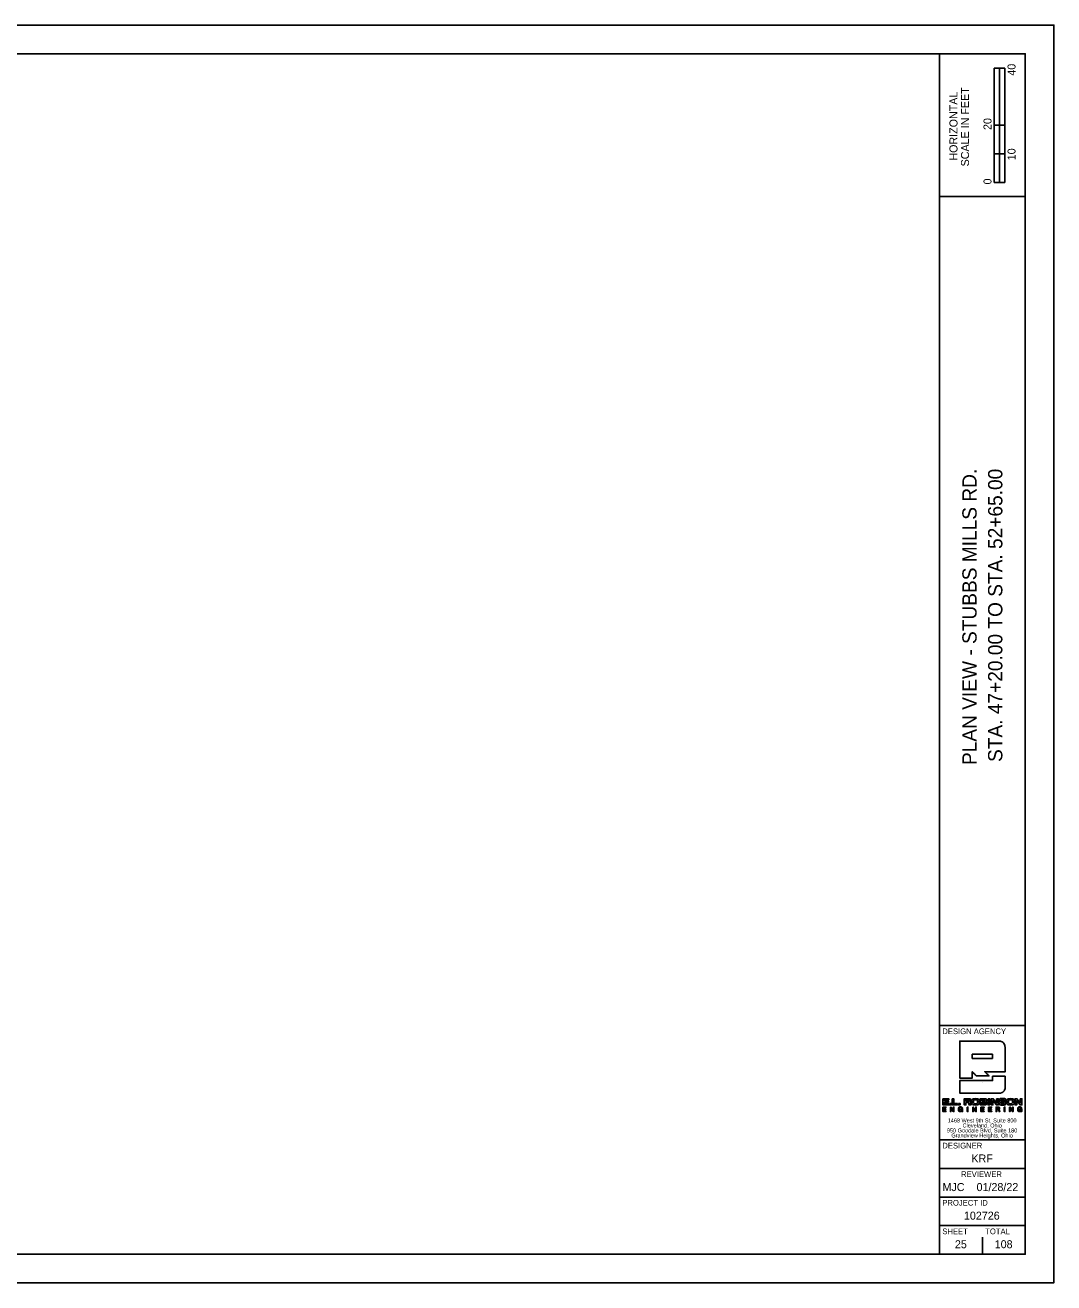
# Model space of a CAD drawing. Extents: x -1.8 to 34.2, y 5.2 to 27.2.
# Drawn here: x 16.19 to 34.18, y 5.18 to 27.18 of the extents above; entities that cross this region are included whole.
import ezdxf

# ---------------------------------------------------------------- set-up
doc = ezdxf.new("R2010")
doc.units = 0
for name, color, linetype in [('SH_Border', 7, 'Continuous'), ('SH_Cut_Line', 7, 'Continuous'), ('SH_Data', 7, 'Continuous')]:
    doc.layers.add(name, color=color, linetype=linetype)

msp = doc.modelspace()

# ---------------------------------------------------------------- linework, layer by layer
at = {"layer": 'SH_Border'}
for p, q in [((32.177, 5.678), (32.177, 26.678)), ((32.177, 24.178), (33.677, 24.178)), ((32.177, 9.678), (33.677, 9.678)), ((32.177, 7.678), (33.677, 7.678)), ((32.177, 7.178), (33.677, 7.178)), ((32.177, 6.678), (33.677, 6.678)), ((32.177, 6.178), (33.677, 6.178))]:
    msp.add_line(p, q, dxfattribs=at)
msp.add_lwpolyline([(1.677, 26.678), (33.677, 26.678), (33.677, 5.678), (1.677, 5.678)], close=True, dxfattribs=at)
at = {"layer": 'SH_Cut_Line'}
msp.add_lwpolyline([(0.177, 5.178), (34.177, 5.178), (34.177, 27.178), (0.177, 27.178)], close=True, dxfattribs=at)
at = {"layer": 'SH_Data'}
for p, q in [((33.133, 24.428), (33.133, 26.428)), ((33.321, 26.428), (33.133, 26.428)), ((33.133, 25.428), (33.133, 26.428)), ((33.133, 26.428), (33.227, 26.428)), ((33.227, 26.428), (33.228, 26.428)), ((33.228, 26.428), (33.228, 25.428)), ((33.321, 26.428), (33.321, 24.428)), ((33.228, 25.428), (33.133, 25.428)), ((33.32, 25.428), (33.227, 25.428)), ((33.227, 25.428), (33.227, 24.928)), ((33.32, 24.928), (33.32, 25.428)), ((33.227, 24.928), (33.133, 24.928)), ((33.133, 24.928), (33.133, 24.428)), ((33.227, 24.428), (33.227, 24.928)), ((33.227, 24.928), (33.32, 24.928)), ((33.321, 24.428), (33.133, 24.428)), ((33.133, 24.428), (33.227, 24.428)), ((33.106, 9.18), (32.751, 9.18)), ((32.751, 9.18), (32.751, 9.103)), ((32.751, 9.103), (33.106, 9.103)), ((33.106, 9.103), (33.106, 9.18)), ((32.927, 8.678), (32.927, 8.678)), ((32.639, 8.378), (32.639, 8.351)), ((32.92, 8.379), (32.92, 8.356)), ((32.92, 8.337), (32.92, 8.311)), ((33.178, 8.243), (33.178, 8.216)), ((33.178, 8.216), (33.2, 8.216)), ((32.927, 5.678), (32.927, 5.978)), ((32.552, 5.853), (32.552, 5.853))]:
    msp.add_line(p, q, dxfattribs=at)
for points in [[(32.236, 8.399), (32.338, 8.399), (32.338, 8.378), (32.266, 8.378), (32.266, 8.356), (32.334, 8.356), (32.334, 8.336), (32.266, 8.336), (32.266, 8.311), (32.339, 8.311), (32.339, 8.29), (32.236, 8.29), (32.236, 8.399)], [(32.397, 8.399), (32.426, 8.399), (32.426, 8.312), (32.492, 8.312), (32.492, 8.29), (32.397, 8.29), (32.397, 8.399)], [(33.028, 8.399), (33.057, 8.399), (33.057, 8.29), (33.028, 8.29), (33.028, 8.399)], [(33.176, 8.399), (33.204, 8.399), (33.204, 8.29), (33.172, 8.29), (33.113, 8.366), (33.113, 8.366), (33.113, 8.29), (33.084, 8.29), (33.084, 8.399), (33.118, 8.399), (33.175, 8.323), (33.176, 8.323), (33.176, 8.399)], [(33.59, 8.399), (33.618, 8.399), (33.618, 8.29), (33.586, 8.29), (33.527, 8.366), (33.527, 8.366), (33.527, 8.29), (33.498, 8.29), (33.498, 8.399), (33.532, 8.399), (33.589, 8.323), (33.59, 8.323), (33.59, 8.399)], [(32.236, 8.252), (32.29, 8.252), (32.29, 8.243), (32.247, 8.243), (32.247, 8.218), (32.287, 8.218), (32.287, 8.21), (32.247, 8.21), (32.247, 8.183), (32.291, 8.183), (32.291, 8.174), (32.236, 8.174), (32.236, 8.252)], [(32.352, 8.316), (32.381, 8.316), (32.381, 8.29), (32.352, 8.29), (32.352, 8.316)], [(32.368, 8.252), (32.379, 8.252), (32.421, 8.189), (32.421, 8.189), (32.421, 8.252), (32.431, 8.252), (32.431, 8.174), (32.419, 8.174), (32.378, 8.237), (32.378, 8.237), (32.378, 8.174), (32.368, 8.174), (32.368, 8.252)], [(32.508, 8.316), (32.537, 8.316), (32.537, 8.29), (32.508, 8.29), (32.508, 8.316)], [(32.664, 8.252), (32.674, 8.252), (32.674, 8.174), (32.664, 8.174), (32.664, 8.252)], [(32.758, 8.252), (32.769, 8.252), (32.81, 8.189), (32.81, 8.189), (32.81, 8.252), (32.82, 8.252), (32.82, 8.174), (32.809, 8.174), (32.768, 8.237), (32.767, 8.237), (32.767, 8.174), (32.758, 8.174), (32.758, 8.252)], [(32.903, 8.252), (32.957, 8.252), (32.957, 8.243), (32.914, 8.243), (32.914, 8.218), (32.954, 8.218), (32.954, 8.21), (32.914, 8.21), (32.914, 8.183), (32.958, 8.183), (32.958, 8.174), (32.903, 8.174), (32.903, 8.252)], [(33.035, 8.252), (33.089, 8.252), (33.089, 8.243), (33.046, 8.243), (33.046, 8.218), (33.086, 8.218), (33.086, 8.21), (33.046, 8.21), (33.046, 8.183), (33.09, 8.183), (33.09, 8.174), (33.035, 8.174), (33.035, 8.252)], [(33.309, 8.252), (33.32, 8.252), (33.32, 8.174), (33.309, 8.174), (33.309, 8.252)], [(33.403, 8.252), (33.414, 8.252), (33.455, 8.189), (33.456, 8.189), (33.456, 8.252), (33.465, 8.252), (33.465, 8.174), (33.454, 8.174), (33.413, 8.237), (33.413, 8.237), (33.413, 8.174), (33.403, 8.174), (33.403, 8.252)]]:
    msp.add_lwpolyline(points, dxfattribs=at)
for points, degree in [([(32.533, 8.76), (32.533, 8.763), (32.533, 9.402), (32.533, 9.405)], 2), ([(32.533, 9.405), (32.536, 9.405), (33.207, 9.405), (33.21, 9.405), (33.273, 9.405), (33.324, 9.354), (33.324, 9.291)], 3), ([(33.324, 9.291), (33.324, 9.289), (33.324, 8.871), (33.324, 8.869)], 2), ([(32.751, 8.869), (32.751, 8.869), (32.751, 8.761), (32.751, 8.76)], 2), ([(32.822, 8.798), (32.822, 8.798), (32.751, 8.869), (32.751, 8.869)], 2), ([(33.324, 8.869), (33.322, 8.869), (32.971, 8.869), (32.97, 8.869)], 2), ([(32.97, 8.869), (32.97, 8.869), (33.043, 8.798), (33.043, 8.798)], 2), ([(32.751, 8.76), (32.75, 8.76), (32.534, 8.76), (32.533, 8.76)], 2), ([(33.106, 8.792), (33.106, 8.792), (33.324, 8.792), (33.324, 8.792), (33.324, 8.792), (33.324, 8.61), (33.324, 8.61), (33.324, 8.548), (33.273, 8.497), (33.21, 8.497), (33.21, 8.497), (32.533, 8.497), (32.533, 8.497), (32.533, 8.497), (32.533, 8.715), (32.533, 8.715), (32.533, 8.715), (33.106, 8.715), (33.106, 8.715), (33.106, 8.715), (33.106, 8.792), (33.106, 8.792)], 3), ([(33.043, 8.798), (33.042, 8.798), (32.823, 8.798), (32.822, 8.798)], 2), ([(32.61, 8.399), (32.61, 8.399), (32.688, 8.399), (32.689, 8.399), (32.719, 8.399), (32.722, 8.38), (32.723, 8.369)], 3), ([(32.61, 8.29), (32.61, 8.291), (32.61, 8.398), (32.61, 8.399)], 2), ([(32.639, 8.351), (32.639, 8.351), (32.678, 8.351), (32.678, 8.351), (32.685, 8.351), (32.693, 8.354), (32.693, 8.365), (32.693, 8.375), (32.684, 8.378), (32.677, 8.378), (32.677, 8.378), (32.639, 8.378), (32.639, 8.378), (32.639, 8.378), (32.639, 8.351), (32.639, 8.351)], 3), ([(32.639, 8.351), (32.652, 8.351), (32.665, 8.351), (32.685, 8.351), (32.693, 8.354), (32.693, 8.375), (32.684, 8.378), (32.664, 8.378), (32.652, 8.378), (32.639, 8.378)], 3), ([(32.723, 8.369), (32.721, 8.357), (32.719, 8.348), (32.706, 8.343)], 2), ([(32.808, 8.287), (32.749, 8.287), (32.744, 8.322), (32.742, 8.345), (32.74, 8.367), (32.749, 8.402), (32.808, 8.402)], 3), ([(32.808, 8.308), (32.835, 8.308), (32.844, 8.328), (32.844, 8.345), (32.844, 8.361), (32.835, 8.381), (32.808, 8.381), (32.781, 8.381), (32.772, 8.361), (32.772, 8.345), (32.772, 8.328), (32.781, 8.308), (32.808, 8.308)], 3), ([(32.808, 8.381), (32.781, 8.381), (32.772, 8.361), (32.772, 8.345), (32.772, 8.328), (32.781, 8.308), (32.808, 8.308)], 3), ([(32.808, 8.402), (32.866, 8.402), (32.872, 8.367), (32.874, 8.344), (32.876, 8.322), (32.866, 8.287), (32.808, 8.287)], 3), ([(32.808, 8.308), (32.835, 8.308), (32.844, 8.328), (32.844, 8.345), (32.844, 8.361), (32.835, 8.381), (32.808, 8.381)], 3), ([(32.891, 8.399), (32.891, 8.399), (32.972, 8.399), (32.972, 8.399)], 2), ([(32.891, 8.29), (32.891, 8.291), (32.891, 8.398), (32.891, 8.399)], 2), ([(32.92, 8.356), (32.92, 8.356), (32.961, 8.356), (32.961, 8.356), (32.968, 8.356), (32.972, 8.359), (32.972, 8.367), (32.972, 8.374), (32.969, 8.379), (32.957, 8.379), (32.957, 8.379), (32.92, 8.379), (32.92, 8.379), (32.92, 8.379), (32.92, 8.356), (32.92, 8.356)], 3), ([(32.92, 8.356), (32.934, 8.356), (32.948, 8.356), (32.968, 8.359), (32.968, 8.361), (32.969, 8.374), (32.969, 8.379), (32.945, 8.379), (32.932, 8.379), (32.92, 8.379)], 3), ([(32.972, 8.399), (32.987, 8.395), (33.003, 8.392), (33.003, 8.372)], 2), ([(33.003, 8.372), (33.001, 8.364), (32.999, 8.353), (32.988, 8.35)], 2), ([(33.303, 8.367), (33.301, 8.382), (33.288, 8.383), (33.276, 8.383), (33.263, 8.383), (33.256, 8.378), (33.256, 8.37), (33.256, 8.365), (33.26, 8.361), (33.268, 8.36), (33.268, 8.36), (33.305, 8.354), (33.305, 8.354), (33.325, 8.351), (33.34, 8.343), (33.34, 8.324), (33.34, 8.303), (33.326, 8.287), (33.283, 8.287), (33.257, 8.287), (33.222, 8.291), (33.222, 8.324), (33.222, 8.324), (33.255, 8.324), (33.255, 8.324), (33.256, 8.31), (33.271, 8.307), (33.283, 8.307), (33.297, 8.307), (33.307, 8.311), (33.307, 8.321), (33.307, 8.329), (33.3, 8.331), (33.288, 8.333), (33.288, 8.333), (33.261, 8.337), (33.261, 8.337), (33.242, 8.34), (33.224, 8.346), (33.224, 8.368), (33.224, 8.392), (33.244, 8.402), (33.278, 8.402), (33.3, 8.402), (33.334, 8.398), (33.336, 8.367), (33.336, 8.367), (33.303, 8.367), (33.303, 8.367)], 3), ([(33.418, 8.287), (33.36, 8.287), (33.354, 8.322), (33.353, 8.345), (33.351, 8.367), (33.36, 8.402), (33.418, 8.402)], 3), ([(33.418, 8.308), (33.445, 8.308), (33.455, 8.328), (33.455, 8.345), (33.455, 8.361), (33.445, 8.381), (33.418, 8.381), (33.392, 8.381), (33.382, 8.361), (33.382, 8.345), (33.382, 8.328), (33.392, 8.308), (33.418, 8.308)], 3), ([(33.418, 8.381), (33.392, 8.381), (33.382, 8.361), (33.382, 8.345), (33.382, 8.328), (33.392, 8.308), (33.418, 8.308)], 3), ([(33.418, 8.402), (33.477, 8.402), (33.483, 8.367), (33.484, 8.344), (33.486, 8.322), (33.477, 8.287), (33.418, 8.287)], 3), ([(33.418, 8.308), (33.445, 8.308), (33.455, 8.328), (33.455, 8.345), (33.455, 8.361), (33.445, 8.381), (33.418, 8.381)], 3), ([(32.572, 8.184), (32.566, 8.175), (32.556, 8.172), (32.547, 8.172), (32.524, 8.172), (32.51, 8.191), (32.51, 8.211), (32.51, 8.234), (32.522, 8.254), (32.547, 8.254), (32.564, 8.254), (32.578, 8.246), (32.581, 8.228), (32.581, 8.228), (32.57, 8.228), (32.57, 8.228), (32.568, 8.24), (32.559, 8.245), (32.547, 8.245), (32.528, 8.245), (32.52, 8.229), (32.52, 8.212), (32.52, 8.196), (32.53, 8.181), (32.547, 8.181), (32.563, 8.181), (32.573, 8.192), (32.572, 8.206), (32.572, 8.206), (32.547, 8.206), (32.547, 8.206), (32.547, 8.206), (32.547, 8.215), (32.547, 8.215), (32.547, 8.215), (32.582, 8.215), (32.582, 8.215), (32.582, 8.215), (32.582, 8.174), (32.582, 8.174), (32.582, 8.174), (32.575, 8.174), (32.575, 8.174), (32.575, 8.174), (32.572, 8.184), (32.572, 8.184)], 3), ([(32.639, 8.29), (32.639, 8.29), (32.61, 8.29), (32.61, 8.29)], 2), ([(32.676, 8.33), (32.676, 8.33), (32.64, 8.33), (32.639, 8.33)], 2), ([(32.639, 8.33), (32.639, 8.33), (32.639, 8.29), (32.639, 8.29)], 2), ([(32.695, 8.29), (32.693, 8.296), (32.693, 8.3), (32.692, 8.311), (32.692, 8.326), (32.685, 8.328), (32.676, 8.33)], 3), ([(32.727, 8.29), (32.727, 8.29), (32.695, 8.29), (32.695, 8.29)], 2), ([(32.706, 8.343), (32.706, 8.343), (32.706, 8.343), (32.706, 8.343)], 2), ([(32.706, 8.343), (32.719, 8.341), (32.721, 8.324), (32.721, 8.314)], 2), ([(32.721, 8.314), (32.721, 8.308), (32.725, 8.297), (32.727, 8.29)], 2), ([(33.006, 8.323), (33.004, 8.309), (33.001, 8.29), (32.968, 8.29), (32.968, 8.29), (32.891, 8.29), (32.891, 8.29)], 3), ([(32.92, 8.311), (32.92, 8.311), (32.964, 8.311), (32.964, 8.311), (32.973, 8.311), (32.976, 8.317), (32.976, 8.324), (32.976, 8.332), (32.971, 8.337), (32.961, 8.337), (32.961, 8.337), (32.92, 8.337), (32.92, 8.337), (32.92, 8.337), (32.92, 8.311), (32.92, 8.311)], 3), ([(32.92, 8.311), (32.935, 8.311), (32.949, 8.311), (32.973, 8.311), (32.976, 8.317), (32.976, 8.332), (32.971, 8.337), (32.947, 8.337), (32.934, 8.337), (32.92, 8.337)], 3), ([(32.988, 8.35), (32.988, 8.35), (32.988, 8.349), (32.988, 8.349)], 2), ([(32.988, 8.349), (33.001, 8.347), (33.004, 8.334), (33.006, 8.323)], 2), ([(33.167, 8.252), (33.168, 8.252), (33.204, 8.252), (33.204, 8.252), (33.219, 8.252), (33.228, 8.244), (33.228, 8.232)], 3), ([(33.167, 8.174), (33.167, 8.174), (33.167, 8.252), (33.167, 8.252)], 2), ([(33.178, 8.174), (33.178, 8.174), (33.168, 8.174), (33.167, 8.174)], 2), ([(33.2, 8.216), (33.209, 8.216), (33.218, 8.219), (33.218, 8.23), (33.218, 8.238), (33.214, 8.243), (33.204, 8.243), (33.204, 8.243), (33.178, 8.243), (33.178, 8.243), (33.178, 8.243), (33.178, 8.216), (33.178, 8.216), (33.178, 8.216), (33.2, 8.216), (33.2, 8.216)], 3), ([(33.2, 8.216), (33.209, 8.216), (33.218, 8.219), (33.218, 8.238), (33.214, 8.243), (33.195, 8.243), (33.187, 8.243), (33.178, 8.243)], 3), ([(33.216, 8.193), (33.215, 8.201), (33.213, 8.207), (33.203, 8.207), (33.203, 8.207), (33.178, 8.207), (33.178, 8.207)], 3), ([(33.178, 8.207), (33.178, 8.207), (33.178, 8.174), (33.178, 8.174)], 2), ([(33.228, 8.232), (33.226, 8.223), (33.224, 8.214), (33.215, 8.212)], 2), ([(33.215, 8.212), (33.215, 8.212), (33.215, 8.212), (33.215, 8.212)], 2), ([(33.215, 8.212), (33.221, 8.207), (33.223, 8.202), (33.225, 8.195)], 2), ([(33.219, 8.174), (33.219, 8.177), (33.218, 8.185), (33.216, 8.193)], 2), ([(33.231, 8.174), (33.231, 8.174), (33.219, 8.174), (33.219, 8.174)], 2), ([(33.225, 8.195), (33.226, 8.188), (33.229, 8.18), (33.231, 8.174)], 2), ([(33.607, 8.184), (33.601, 8.175), (33.591, 8.172), (33.582, 8.172), (33.559, 8.172), (33.545, 8.191), (33.545, 8.211), (33.545, 8.234), (33.557, 8.254), (33.582, 8.254), (33.599, 8.254), (33.613, 8.246), (33.616, 8.228), (33.616, 8.228), (33.605, 8.228), (33.605, 8.228), (33.603, 8.24), (33.594, 8.245), (33.582, 8.245), (33.563, 8.245), (33.555, 8.229), (33.555, 8.212), (33.555, 8.196), (33.565, 8.181), (33.582, 8.181), (33.598, 8.181), (33.608, 8.192), (33.607, 8.206), (33.607, 8.206), (33.582, 8.206), (33.582, 8.206), (33.582, 8.206), (33.582, 8.215), (33.582, 8.215), (33.582, 8.215), (33.616, 8.215), (33.616, 8.215), (33.616, 8.215), (33.616, 8.174), (33.616, 8.174), (33.616, 8.174), (33.61, 8.174), (33.61, 8.174), (33.61, 8.174), (33.607, 8.184), (33.607, 8.184)], 3)]:
    msp.add_open_spline(points, degree=degree, dxfattribs=at)

# ---------------------------------------------------------------- texts
for s, height, p in [('40', 0.14, (33.507, 26.294)), ('HORIZONTAL', 0.14, (32.492, 24.808)), ('SCALE IN FEET', 0.14, (32.694, 24.707)), ('20', 0.14, (33.087, 25.344)), ('10', 0.14, (33.507, 24.814)), ('0', 0.14, (33.087, 24.391)), ('PLAN VIEW - STUBBS MILLS RD.', 0.25, (32.827, 14.235)), ('STA. 47+20.00 TO STA. 52+65.00', 0.25, (33.277, 14.289))]:
    msp.add_text(s, height=height, rotation=90, dxfattribs=at).set_placement(p)
for s, height, p in [('DESIGN AGENCY', 0.1, (32.227, 9.528)), ('1468 West 9th St, Suite 800', 0.07, (32.321, 7.983)), ('Cleveland, Ohio', 0.07, (32.581, 7.895)), ('950 Goodale Blvd, Suite 180', 0.07, (32.307, 7.808)), ('Grandview Heights, Ohio', 0.07, (32.385, 7.72)), ('DESIGNER', 0.1, (32.227, 7.528)), ('KRF', 0.14, (32.736, 7.283)), ('REVIEWER', 0.1, (32.555, 7.028)), ('MJC', 0.14, (32.23, 6.783)), ('01/28/22', 0.14, (32.826, 6.783)), ('PROJECT ID', 0.1, (32.227, 6.528)), ('102726', 0.14, (32.605, 6.283)), ('SHEET', 0.1, (32.227, 6.028)), ('TOTAL', 0.1, (32.977, 6.028)), ('25', 0.14, (32.447, 5.783)), ('108', 0.14, (33.143, 5.783))]:
    msp.add_text(s, height=height, dxfattribs=at).set_placement(p)

doc.saveas('drawing.dxf')
